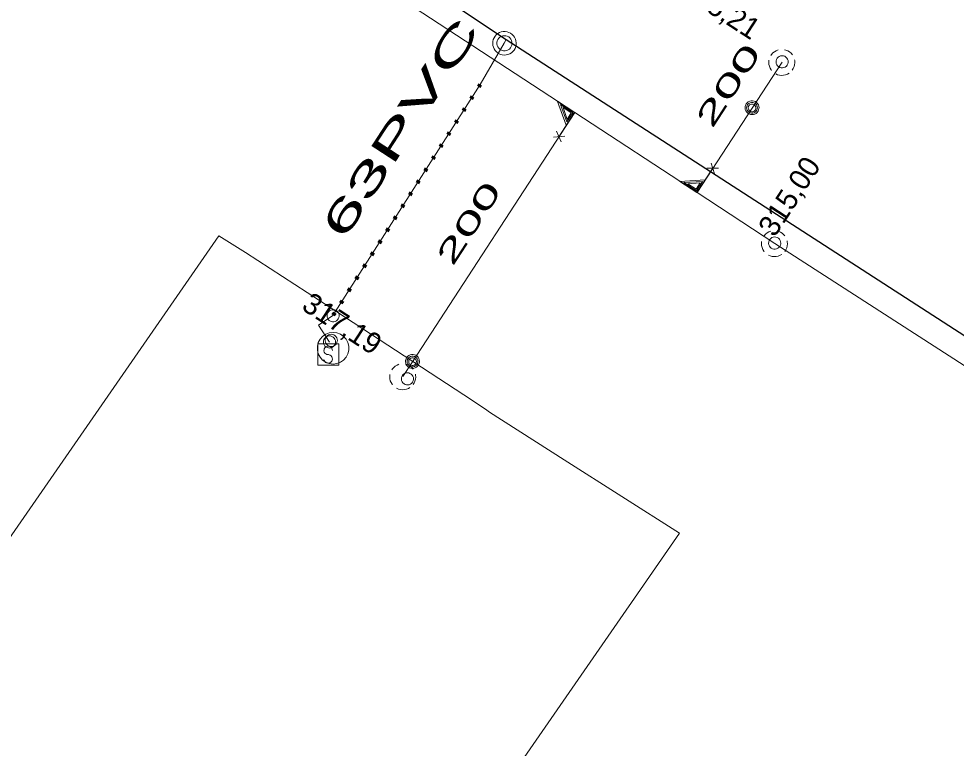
# Model space of a CAD drawing. Extents: x -742876 to -742577, y -1054710 to -1054452.
# Drawn here: x -742678.08 to -742642.52, y -1054545.47 to -1054517.81 of the extents above; entities that cross this region are included whole.
import ezdxf

# ---------------------------------------------------------------- set-up
doc = ezdxf.new("R2010")
doc.units = 0
doc.header["$LTSCALE"] = 0.36
doc.linetypes.add('DOTTED', pattern=[1.5, 0.3, -1.2])
doc.linetypes.add('MEDIUM_DASHED', pattern=[4.5, 3, -1.5])
for name, color, linetype, lineweight in [('1', 7, 'MEDIUM_DASHED', 25), ('18', 7, 'Continuous', 13), ('20', 7, 'Continuous', 13), ('49', 7, 'Continuous', 13), ('8', 7, 'Continuous', 13)]:
    doc.layers.add(name, color=color, linetype=linetype, lineweight=lineweight)

msp = doc.modelspace()

# ---------------------------------------------------------------- linework, layer by layer
at = {"layer": '18'}
for p, q in [((-742657.803, -1054522.305), (-742657.376, -1054522.264)), ((-742657.512, -1054522.48), (-742657.689, -1054522.073)), ((-742651.823, -1054523.289), (-742651.69, -1054523.698)), ((-742651.547, -1054523.484), (-742651.991, -1054523.485))]:
    msp.add_line(p, q, dxfattribs=at)
for points in [[(-742649.282, -1054518.997), (-742649.353, -1054519.025), (-742649.419, -1054519.064), (-742649.48, -1054519.112), (-742649.531, -1054519.169), (-742649.554, -1054519.203)], [(-742648.74, -1054519.18), (-742648.791, -1054519.122), (-742648.848, -1054519.072), (-742648.914, -1054519.031), (-742648.985, -1054519.002), (-742649.034, -1054518.988)], [(-742649.627, -1054519.389), (-742649.632, -1054519.466), (-742649.627, -1054519.543), (-742649.61, -1054519.618), (-742649.581, -1054519.689), (-742649.541, -1054519.755), (-742649.526, -1054519.777)], [(-742648.745, -1054519.766), (-742648.705, -1054519.701), (-742648.674, -1054519.631), (-742648.654, -1054519.556), (-742648.647, -1054519.48), (-742648.652, -1054519.403), (-742648.657, -1054519.368)], [(-742649.369, -1054519.906), (-742649.299, -1054519.937), (-742649.223, -1054519.956), (-742649.147, -1054519.963), (-742649.071, -1054519.958), (-742648.995, -1054519.941), (-742648.924, -1054519.913), (-742648.864, -1054519.878)], [(-742657.598, -1054522.286), (-742656.998, -1054521.368), (-742657.643, -1054520.946), (-742657.314, -1054521.852)], [(-742657.292, -1054521.725), (-742657.065, -1054521.377), (-742657.538, -1054521.068), (-742657.293, -1054521.726)], [(-742657.286, -1054521.629), (-742657.126, -1054521.386), (-742657.437, -1054521.183), (-742657.284, -1054521.63)], [(-742651.76, -1054523.485), (-742652.36, -1054524.401), (-742653.004, -1054523.98), (-742652.043, -1054523.917)], [(-742652.15, -1054523.99), (-742652.377, -1054524.337), (-742652.851, -1054524.027), (-742652.149, -1054523.988)], [(-742652.235, -1054524.033), (-742652.395, -1054524.278), (-742652.706, -1054524.074), (-742652.234, -1054524.034)], [(-742649.563, -1054525.867), (-742649.634, -1054525.895), (-742649.701, -1054525.934), (-742649.761, -1054525.982), (-742649.812, -1054526.039), (-742649.836, -1054526.073)], [(-742649.022, -1054526.05), (-742649.072, -1054525.992), (-742649.13, -1054525.942), (-742649.195, -1054525.901), (-742649.266, -1054525.872), (-742649.315, -1054525.858)], [(-742649.908, -1054526.259), (-742649.914, -1054526.336), (-742649.909, -1054526.413), (-742649.892, -1054526.488), (-742649.863, -1054526.559), (-742649.823, -1054526.625), (-742649.807, -1054526.647)], [(-742649.027, -1054526.636), (-742648.986, -1054526.571), (-742648.955, -1054526.501), (-742648.936, -1054526.426), (-742648.928, -1054526.35), (-742648.933, -1054526.273), (-742648.939, -1054526.238)], [(-742649.65, -1054526.776), (-742649.58, -1054526.807), (-742649.505, -1054526.826), (-742649.429, -1054526.833), (-742649.352, -1054526.828), (-742649.277, -1054526.811), (-742649.205, -1054526.783), (-742649.145, -1054526.748)], [(-742663.663, -1054530.916), (-742663.734, -1054530.944), (-742663.801, -1054530.983), (-742663.861, -1054531.031), (-742663.912, -1054531.088), (-742663.936, -1054531.122)], [(-742663.122, -1054531.099), (-742663.172, -1054531.041), (-742663.23, -1054530.991), (-742663.295, -1054530.95), (-742663.366, -1054530.921), (-742663.415, -1054530.907)], [(-742664.008, -1054531.308), (-742664.014, -1054531.385), (-742664.009, -1054531.462), (-742663.992, -1054531.537), (-742663.963, -1054531.608), (-742663.923, -1054531.674), (-742663.907, -1054531.696)], [(-742663.127, -1054531.685), (-742663.086, -1054531.62), (-742663.055, -1054531.55), (-742663.036, -1054531.475), (-742663.028, -1054531.399), (-742663.033, -1054531.322), (-742663.039, -1054531.287)], [(-742663.75, -1054531.825), (-742663.68, -1054531.856), (-742663.605, -1054531.875), (-742663.529, -1054531.882), (-742663.452, -1054531.877), (-742663.377, -1054531.86), (-742663.305, -1054531.832), (-742663.245, -1054531.797)]]:
    msp.add_lwpolyline(points, dxfattribs=at)
for points in [[(-742648.897, -1054519.449), (-742648.904, -1054519.397), (-742648.921, -1054519.347), (-742648.95, -1054519.303), (-742648.988, -1054519.266), (-742649.032, -1054519.239), (-742649.083, -1054519.223), (-742649.135, -1054519.218), (-742649.186, -1054519.225), (-742649.235, -1054519.244), (-742649.279, -1054519.274), (-742649.315, -1054519.313), (-742649.341, -1054519.358), (-742649.355, -1054519.409), (-742649.358, -1054519.461), (-742649.35, -1054519.513), (-742649.33, -1054519.561), (-742649.299, -1054519.604), (-742649.26, -1054519.639), (-742649.213, -1054519.663), (-742649.163, -1054519.677), (-742649.11, -1054519.679), (-742649.059, -1054519.669), (-742649.011, -1054519.647), (-742648.968, -1054519.615), (-742648.936, -1054519.575), (-742648.912, -1054519.528), (-742648.899, -1054519.477)], [(-742650.006, -1054521.187), (-742650.012, -1054521.131), (-742650.029, -1054521.078), (-742650.058, -1054521.029), (-742650.096, -1054520.988), (-742650.142, -1054520.956), (-742650.194, -1054520.934), (-742650.249, -1054520.923), (-742650.305, -1054520.925), (-742650.36, -1054520.938), (-742650.411, -1054520.963), (-742650.455, -1054520.998), (-742650.491, -1054521.041), (-742650.516, -1054521.091), (-742650.531, -1054521.146), (-742650.534, -1054521.202), (-742650.525, -1054521.257), (-742650.504, -1054521.31), (-742650.473, -1054521.356), (-742650.433, -1054521.395), (-742650.385, -1054521.425), (-742650.332, -1054521.444), (-742650.276, -1054521.451), (-742650.22, -1054521.447), (-742650.166, -1054521.43), (-742650.117, -1054521.403), (-742650.075, -1054521.365), (-742650.042, -1054521.32), (-742650.019, -1054521.269), (-742650.007, -1054521.214)], [(-742650.065, -1054521.19), (-742650.071, -1054521.141), (-742650.089, -1054521.095), (-742650.117, -1054521.054), (-742650.154, -1054521.021), (-742650.198, -1054520.999), (-742650.246, -1054520.987), (-742650.295, -1054520.987), (-742650.343, -1054520.999), (-742650.387, -1054521.022), (-742650.424, -1054521.055), (-742650.452, -1054521.096), (-742650.469, -1054521.143), (-742650.475, -1054521.192), (-742650.468, -1054521.241), (-742650.45, -1054521.287), (-742650.422, -1054521.327), (-742650.385, -1054521.36), (-742650.341, -1054521.382), (-742650.292, -1054521.394), (-742650.243, -1054521.393), (-742650.195, -1054521.381), (-742650.152, -1054521.357), (-742650.115, -1054521.324), (-742650.087, -1054521.283), (-742650.071, -1054521.236)], [(-742650.124, -1054521.194), (-742650.13, -1054521.152), (-742650.147, -1054521.114), (-742650.175, -1054521.083), (-742650.21, -1054521.06), (-742650.25, -1054521.049), (-742650.292, -1054521.049), (-742650.332, -1054521.061), (-742650.367, -1054521.084), (-742650.394, -1054521.116), (-742650.411, -1054521.154), (-742650.416, -1054521.195), (-742650.41, -1054521.237), (-742650.392, -1054521.274), (-742650.364, -1054521.306), (-742650.328, -1054521.328), (-742650.288, -1054521.339), (-742650.246, -1054521.338), (-742650.206, -1054521.325), (-742650.172, -1054521.302), (-742650.145, -1054521.269), (-742650.129, -1054521.231)], [(-742649.179, -1054526.319), (-742649.185, -1054526.267), (-742649.203, -1054526.217), (-742649.231, -1054526.173), (-742649.269, -1054526.136), (-742649.314, -1054526.109), (-742649.364, -1054526.093), (-742649.416, -1054526.088), (-742649.468, -1054526.095), (-742649.517, -1054526.114), (-742649.561, -1054526.144), (-742649.596, -1054526.183), (-742649.622, -1054526.228), (-742649.637, -1054526.279), (-742649.64, -1054526.331), (-742649.632, -1054526.383), (-742649.611, -1054526.431), (-742649.581, -1054526.474), (-742649.541, -1054526.509), (-742649.495, -1054526.533), (-742649.444, -1054526.547), (-742649.392, -1054526.549), (-742649.34, -1054526.539), (-742649.292, -1054526.517), (-742649.25, -1054526.485), (-742649.217, -1054526.445), (-742649.193, -1054526.398), (-742649.181, -1054526.347)], [(-742662.885, -1054530.807), (-742662.891, -1054530.751), (-742662.907, -1054530.698), (-742662.936, -1054530.649), (-742662.975, -1054530.608), (-742663.021, -1054530.576), (-742663.073, -1054530.554), (-742663.128, -1054530.543), (-742663.184, -1054530.545), (-742663.239, -1054530.558), (-742663.289, -1054530.583), (-742663.334, -1054530.618), (-742663.37, -1054530.661), (-742663.395, -1054530.711), (-742663.41, -1054530.766), (-742663.413, -1054530.822), (-742663.404, -1054530.877), (-742663.383, -1054530.93), (-742663.352, -1054530.976), (-742663.311, -1054531.015), (-742663.264, -1054531.045), (-742663.211, -1054531.064), (-742663.155, -1054531.071), (-742663.098, -1054531.067), (-742663.044, -1054531.05), (-742662.995, -1054531.023), (-742662.954, -1054530.985), (-742662.921, -1054530.94), (-742662.897, -1054530.889), (-742662.886, -1054530.834)], [(-742662.944, -1054530.81), (-742662.95, -1054530.761), (-742662.968, -1054530.715), (-742662.995, -1054530.674), (-742663.032, -1054530.641), (-742663.076, -1054530.619), (-742663.125, -1054530.607), (-742663.174, -1054530.607), (-742663.222, -1054530.619), (-742663.266, -1054530.642), (-742663.303, -1054530.675), (-742663.331, -1054530.716), (-742663.348, -1054530.763), (-742663.353, -1054530.812), (-742663.347, -1054530.861), (-742663.329, -1054530.907), (-742663.301, -1054530.947), (-742663.264, -1054530.98), (-742663.22, -1054531.002), (-742663.171, -1054531.014), (-742663.122, -1054531.013), (-742663.074, -1054531.001), (-742663.031, -1054530.977), (-742662.994, -1054530.944), (-742662.966, -1054530.903), (-742662.95, -1054530.856)], [(-742663.003, -1054530.814), (-742663.009, -1054530.772), (-742663.026, -1054530.734), (-742663.054, -1054530.703), (-742663.088, -1054530.68), (-742663.129, -1054530.669), (-742663.171, -1054530.669), (-742663.211, -1054530.681), (-742663.245, -1054530.704), (-742663.272, -1054530.736), (-742663.289, -1054530.774), (-742663.294, -1054530.815), (-742663.289, -1054530.857), (-742663.271, -1054530.894), (-742663.243, -1054530.926), (-742663.206, -1054530.948), (-742663.167, -1054530.959), (-742663.125, -1054530.958), (-742663.085, -1054530.945), (-742663.051, -1054530.922), (-742663.024, -1054530.889), (-742663.008, -1054530.851)], [(-742663.108, -1054531.469), (-742663.115, -1054531.417), (-742663.132, -1054531.367), (-742663.161, -1054531.323), (-742663.199, -1054531.286), (-742663.244, -1054531.259), (-742663.294, -1054531.243), (-742663.346, -1054531.238), (-742663.397, -1054531.245), (-742663.446, -1054531.264), (-742663.49, -1054531.294), (-742663.526, -1054531.333), (-742663.552, -1054531.378), (-742663.566, -1054531.429), (-742663.57, -1054531.481), (-742663.561, -1054531.533), (-742663.541, -1054531.581), (-742663.511, -1054531.624), (-742663.471, -1054531.659), (-742663.424, -1054531.683), (-742663.374, -1054531.697), (-742663.321, -1054531.699), (-742663.27, -1054531.689), (-742663.222, -1054531.667), (-742663.179, -1054531.635), (-742663.147, -1054531.595), (-742663.123, -1054531.548), (-742663.11, -1054531.497)]]:
    msp.add_lwpolyline(points, close=True, dxfattribs=at)
at = {"layer": '20'}
for points in [[(-742649.41, -1054526.33), (-742652.355, -1054524.403), (-742656.992, -1054521.37), (-742668.232, -1054514.019), (-742676.87, -1054508.37)], [(-742649.41, -1054526.33), (-742652.355, -1054524.403), (-742656.992, -1054521.37), (-742668.232, -1054514.019), (-742676.87, -1054508.37)], [(-742620.93, -1054544.69), (-742629.588, -1054539.108), (-742635.043, -1054535.591), (-742649.41, -1054526.33)], [(-742620.93, -1054544.69), (-742629.588, -1054539.108), (-742635.043, -1054535.591), (-742649.41, -1054526.33)]]:
    msp.add_lwpolyline(points, dxfattribs=at)
at = {"layer": '49'}
for p, q in [((-742649.129, -1054519.46), (-742650.27, -1054521.2)), ((-742649.129, -1054519.46), (-742650.27, -1054521.2)), ((-742650.27, -1054521.2), (-742652.355, -1054524.403)), ((-742650.27, -1054521.2), (-742652.355, -1054524.403))]:
    msp.add_line(p, q, dxfattribs=at)
msp.add_lwpolyline([(-742663.51, -1054531.379), (-742663.149, -1054530.82), (-742656.992, -1054521.37)], dxfattribs=at)
msp.add_lwpolyline([(-742663.51, -1054531.379), (-742663.149, -1054530.82), (-742656.992, -1054521.37)], dxfattribs=at)
at = {"layer": '8'}
msp.add_line((-742659.59, -1054518.6), (-742659.67, -1054518.74), dxfattribs=at)
at = {"layer": '8', "linetype": 'DOTTED', "lineweight": 140}
msp.add_line((-742660.579, -1054520.31), (-742666.17, -1054529.07), dxfattribs=at)
at = {"layer": '8', "lineweight": 25}
msp.add_lwpolyline([(-742668.59, -1054512.75), (-742661.706, -1054517.203), (-742659.59, -1054518.6), (-742636.057, -1054533.803), (-742635.66, -1054534.06)], dxfattribs=at)
at = {"layer": '8'}
for points in [[(-742659.882, -1054519.133), (-742659.816, -1054519.164), (-742659.745, -1054519.183), (-742659.673, -1054519.191), (-742659.6, -1054519.187), (-742659.528, -1054519.172), (-742659.46, -1054519.145), (-742659.398, -1054519.106), (-742659.342, -1054519.059), (-742659.295, -1054519.003), (-742659.258, -1054518.939), (-742659.232, -1054518.871), (-742659.217, -1054518.799), (-742659.214, -1054518.727), (-742659.223, -1054518.654), (-742659.243, -1054518.583), (-742659.275, -1054518.518), (-742659.318, -1054518.458), (-742659.369, -1054518.406), (-742659.428, -1054518.363), (-742659.494, -1054518.33), (-742659.563, -1054518.308), (-742659.636, -1054518.298), (-742659.709, -1054518.3), (-742659.781, -1054518.314), (-742659.849, -1054518.34), (-742659.913, -1054518.376), (-742659.97, -1054518.422), (-742660.019, -1054518.477), (-742660.057, -1054518.539), (-742660.086, -1054518.606), (-742660.102, -1054518.678), (-742660.107, -1054518.751), (-742660.101, -1054518.824), (-742660.082, -1054518.894), (-742660.051, -1054518.961), (-742660.011, -1054519.022), (-742659.961, -1054519.075), (-742659.903, -1054519.12)], [(-742659.802, -1054518.993), (-742659.749, -1054519.017), (-742659.691, -1054519.029), (-742659.633, -1054519.03), (-742659.576, -1054519.018), (-742659.522, -1054518.996), (-742659.474, -1054518.962), (-742659.433, -1054518.919), (-742659.402, -1054518.869), (-742659.383, -1054518.815), (-742659.374, -1054518.756), (-742659.378, -1054518.698), (-742659.393, -1054518.642), (-742659.42, -1054518.59), (-742659.457, -1054518.543), (-742659.501, -1054518.506), (-742659.553, -1054518.479), (-742659.61, -1054518.463), (-742659.668, -1054518.458), (-742659.726, -1054518.466), (-742659.782, -1054518.485), (-742659.831, -1054518.516), (-742659.875, -1054518.555), (-742659.909, -1054518.603), (-742659.932, -1054518.656), (-742659.945, -1054518.713), (-742659.945, -1054518.772), (-742659.933, -1054518.829), (-742659.911, -1054518.883), (-742659.877, -1054518.931), (-742659.835, -1054518.971)], [(-742666.68, -1054528.5), (-742661.199, -1054532.07), (-742661.1, -1054532.139), (-742660.329, -1054532.659), (-742660.23, -1054532.73), (-742657.392, -1054534.536), (-742653.02, -1054537.32), (-742664.78, -1054554.29), (-742665.522, -1054556.177), (-742665.34, -1054556.31), (-742665.27, -1054557.04), (-742669.27, -1054562.919), (-742679.91, -1054555.73), (-742679.572, -1054555.227), (-742687.149, -1054550.07), (-742670.489, -1054526.04), (-742669.48, -1054526.679), (-742668.079, -1054527.59)], [(-742666.285, -1054529.27), (-742666.238, -1054529.293), (-742666.186, -1054529.305), (-742666.134, -1054529.305), (-742666.082, -1054529.292), (-742666.035, -1054529.269), (-742665.995, -1054529.235), (-742665.963, -1054529.194), (-742665.941, -1054529.147), (-742665.93, -1054529.095), (-742665.932, -1054529.042), (-742665.946, -1054528.992), (-742665.97, -1054528.945), (-742666.005, -1054528.905), (-742666.047, -1054528.875), (-742666.095, -1054528.854), (-742666.147, -1054528.845), (-742666.199, -1054528.848), (-742666.25, -1054528.863), (-742666.295, -1054528.888), (-742666.335, -1054528.924), (-742666.364, -1054528.967), (-742666.384, -1054529.016), (-742666.391, -1054529.068), (-742666.387, -1054529.121), (-742666.371, -1054529.17), (-742666.344, -1054529.216), (-742666.307, -1054529.253)], [(-742666.162, -1054529.706), (-742666.019, -1054529.723), (-742665.883, -1054529.775), (-742665.764, -1054529.857), (-742665.669, -1054529.965), (-742665.601, -1054530.093), (-742665.567, -1054530.234), (-742665.567, -1054530.378), (-742665.601, -1054530.519), (-742665.669, -1054530.647), (-742665.764, -1054530.755), (-742665.884, -1054530.837), (-742666.019, -1054530.889), (-742666.162, -1054530.906), (-742666.306, -1054530.889), (-742666.441, -1054530.837), (-742666.56, -1054530.755), (-742666.656, -1054530.647), (-742666.723, -1054530.519), (-742666.758, -1054530.378), (-742666.758, -1054530.234), (-742666.723, -1054530.093), (-742666.656, -1054529.965), (-742666.56, -1054529.857), (-742666.441, -1054529.775), (-742666.306, -1054529.723)], [(-742665.999, -1054530.009), (-742666.005, -1054529.957), (-742666.022, -1054529.907), (-742666.051, -1054529.863), (-742666.089, -1054529.826), (-742666.134, -1054529.799), (-742666.184, -1054529.783), (-742666.236, -1054529.778), (-742666.288, -1054529.785), (-742666.337, -1054529.804), (-742666.38, -1054529.834), (-742666.416, -1054529.873), (-742666.442, -1054529.918), (-742666.456, -1054529.969), (-742666.46, -1054530.021), (-742666.451, -1054530.073), (-742666.431, -1054530.121), (-742666.401, -1054530.164), (-742666.361, -1054530.199), (-742666.315, -1054530.223), (-742666.264, -1054530.237), (-742666.212, -1054530.239), (-742666.16, -1054530.229), (-742666.112, -1054530.207), (-742666.07, -1054530.175), (-742666.037, -1054530.135), (-742666.013, -1054530.088), (-742666, -1054530.037)], [(-742666.735, -1054530.146), (-742665.946, -1054530.146), (-742665.946, -1054530.946), (-742666.735, -1054530.946)], [(-742666.069, -1054530.069), (-742666.075, -1054530.017), (-742666.093, -1054529.967), (-742666.121, -1054529.923), (-742666.159, -1054529.886), (-742666.204, -1054529.859), (-742666.254, -1054529.843), (-742666.306, -1054529.838), (-742666.358, -1054529.845), (-742666.407, -1054529.864), (-742666.451, -1054529.894), (-742666.486, -1054529.933), (-742666.512, -1054529.978), (-742666.527, -1054530.029), (-742666.53, -1054530.081), (-742666.522, -1054530.133), (-742666.501, -1054530.181), (-742666.471, -1054530.224), (-742666.431, -1054530.259), (-742666.385, -1054530.283), (-742666.334, -1054530.297), (-742666.282, -1054530.299), (-742666.23, -1054530.289), (-742666.182, -1054530.267), (-742666.14, -1054530.235), (-742666.107, -1054530.195), (-742666.083, -1054530.148), (-742666.071, -1054530.097)]]:
    msp.add_lwpolyline(points, close=True, dxfattribs=at)
for points in [[(-742659.67, -1054518.74), (-742660.579, -1054520.31), (-742666.17, -1054529.07)], [(-742666.17, -1054529.07), (-742666.71, -1054529.429), (-742666.3, -1054530.08)], [(-742666.186, -1054530.392), (-742666.191, -1054530.349), (-742666.208, -1054530.308), (-742666.235, -1054530.274), (-742666.272, -1054530.248), (-742666.313, -1054530.233), (-742666.356, -1054530.23), (-742666.399, -1054530.238), (-742666.438, -1054530.258), (-742666.471, -1054530.287), (-742666.494, -1054530.325), (-742666.505, -1054530.367), (-742666.507, -1054530.41), (-742666.495, -1054530.453), (-742666.473, -1054530.49), (-742666.441, -1054530.521), (-742666.402, -1054530.541), (-742666.36, -1054530.55), (-742666.333, -1054530.55)], [(-742666.509, -1054530.729), (-742666.499, -1054530.772), (-742666.477, -1054530.811), (-742666.446, -1054530.842), (-742666.407, -1054530.863), (-742666.365, -1054530.874), (-742666.321, -1054530.872), (-742666.279, -1054530.859), (-742666.242, -1054530.835), (-742666.213, -1054530.802), (-742666.194, -1054530.762), (-742666.186, -1054530.719), (-742666.19, -1054530.675), (-742666.206, -1054530.634), (-742666.232, -1054530.599), (-742666.267, -1054530.572), (-742666.308, -1054530.555), (-742666.333, -1054530.55)]]:
    msp.add_lwpolyline(points, dxfattribs=at)

# ---------------------------------------------------------------- texts
at = {"layer": '1'}
for s, rotation, p in [('315,21', 327, (-742653.048, -1054516.86)), ('315,00', 57, (-742649.414, -1054526.132)), ('317,19', 327, (-742667.401, -1054528.813))]:
    msp.add_text(s, height=0.8, rotation=rotation, dxfattribs=at).set_placement(p)
for s, height, width, p in [('63PVC ', 1.1, 2.05, (-742665.746, -1054526.257)), ('200 ', 0.8, 1.95, (-742651.786, -1054522.013)), ('200 ', 0.8, 1.95, (-742661.63, -1054527.236))]:
    msp.add_text(s, height=height, rotation=57, dxfattribs=dict(at, width=width)).set_placement(p)

doc.saveas('drawing.dxf')
